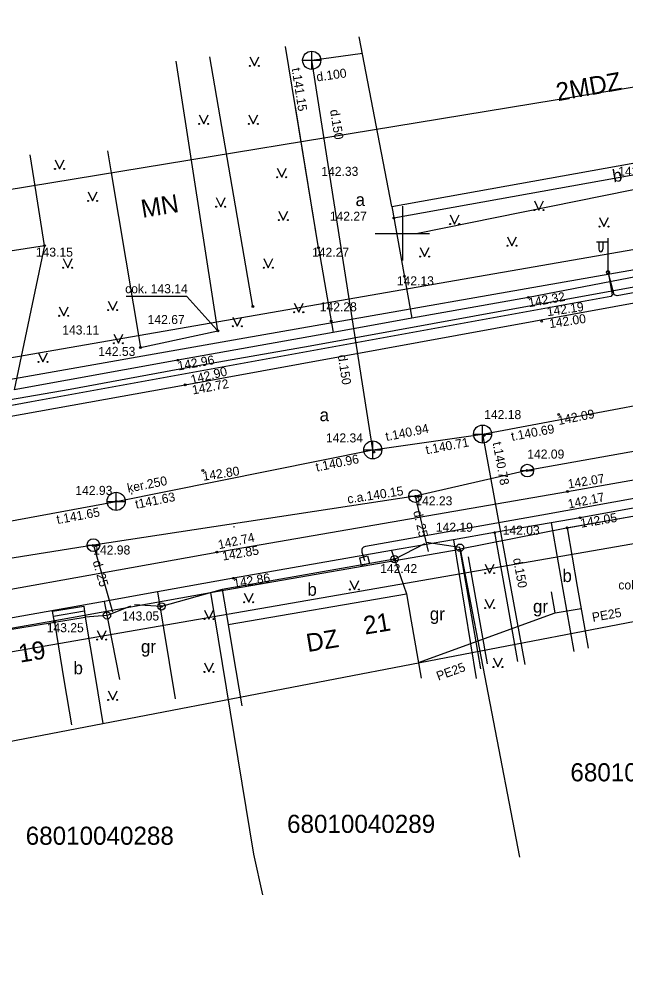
# Model space of a CAD drawing. Extents: x 728492 to 729038, y 272968 to 273171.
# Drawn here: x 728728.8 to 728762.3, y 273058.4 to 273111.8 of the extents above; entities that cross this region are included whole.
import ezdxf

# ---------------------------------------------------------------- set-up
doc = ezdxf.new("R2010")
doc.units = 0
for name, color, linetype in [('APGR_SARK_####_####_#', 7, 'Continuous'), ('APGS_ACRL_####_####_#', 7, 'Continuous'), ('APGS_ELEM_####_####_#', 7, 'Continuous'), ('APGS_VADP_ZSPR_####_I', 7, 'Continuous'), ('BUVE_BDET_####_####_#', 7, 'Continuous'), ('BUVE_BDET_####_TKST_#', 7, 'Continuous'), ('BUVE_EKAS_####_####_#', 7, 'Continuous'), ('BUVE_EKAS_ADRS_TKST_#', 7, 'Continuous'), ('BUVE_EKAS_RAKS_TKST_#', 7, 'Continuous'), ('CELI_CAPM_####_####_#', 7, 'Continuous'), ('CELI_CMAL_####_####_#', 7, 'Continuous'), ('CELI_CSEG_####_TKST_#', 7, 'Continuous'), ('CELI_SEGL_####_####_#', 7, 'Continuous'), ('ELEK_ELEM_####_####_#', 7, 'Continuous'), ('ELEK_VADP_ZSPR_####_I', 7, 'Continuous'), ('GEOD_ELEM_####_####_#', 7, 'Continuous'), ('NORB_ELEM_####_####_#', 7, 'Continuous'), ('NORB_ZOGS_BARJ_####_#', 7, 'Continuous'), ('NORB_ZOGS_KOKA_####_#', 7, 'Continuous'), ('NORB_ZOGS_ZSTP_####_#', 7, 'Continuous'), ('RAMI_UZMR_####_####_#', 7, 'Continuous'), ('RELJ_AATZ_####_TKST_#', 7, 'Continuous'), ('RELJ_ELEM_####_####_#', 7, 'Continuous'), ('ROBZ_KADS_####_TKST_#', 7, 'Continuous'), ('ROBZ_UZMR_####_####_#', 7, 'Continuous'), ('SKAN_ELEM_####_####_#', 7, 'Continuous'), ('SKAN_VADP_PAST_####_#', 7, 'Continuous'), ('SKAN_VADP_PAST_TKST_#', 7, 'Continuous'), ('TERT_DZOG_####_####_#', 7, 'Continuous'), ('TERT_ELEM_####_####_#', 7, 'Continuous'), ('TERT_KRND_####_####_#', 7, 'Continuous'), ('UDTK_ELEM_####_####_#', 7, 'Continuous'), ('UDTK_ELEM_####_TKST_#', 7, 'Continuous'), ('UDTK_VADP_UDEN_####_#', 7, 'Continuous'), ('UDTK_VADP_UDEN_TKST_#', 7, 'Continuous')]:
    doc.layers.add(name, color=color, linetype=linetype)

msp = doc.modelspace()

# ---------------------------------------------------------------- linework, layer by layer
at = {"layer": 'APGR_SARK_####_####_#'}
for points in [[(728813.011, 273107.831), (728678.847, 273084.513)], [(728815.186, 273091.969), (728680.999, 273068.647)]]:
    msp.add_lwpolyline(points, dxfattribs=at)
at = {"layer": 'APGS_ACRL_####_####_#'}
for points in [[(728789.256, 273101.647), (728780.318, 273100.005), (728761.848, 273096.552), (728761.682, 273096.617), (728761.349, 273097.858)], [(728761.587, 273096.618), (728761.498, 273096.52), (728729.511, 273090.707), (728708.292, 273086.771), (728707.787, 273088.186)]]:
    msp.add_lwpolyline(points, dxfattribs=at)
at = {"layer": 'APGS_ELEM_####_####_#'}
for p, q in [((728761.349, 273097.858), (728761.349, 273099.741)), ((728761.349, 273099.525), (728760.714, 273099.52)), ((728760.849, 273099.521), (728760.849, 273099.129)), ((728761.059, 273099.523), (728761.059, 273099.129))]:
    msp.add_line(p, q, dxfattribs=at)
msp.add_circle((728761.349, 273097.858), 0.09, dxfattribs=at)
msp.add_ellipse((728760.954, 273099.129), major_axis=(0, 0.151), ratio=0.695971, start_param=1.570796, end_param=4.712389, dxfattribs=at)
at = {"layer": 'APGS_VADP_ZSPR_####_I'}
for points in [[(728789.256, 273101.647), (728780.318, 273100.005), (728761.848, 273096.552), (728761.682, 273096.617), (728761.633, 273096.789), (728761.349, 273097.858)], [(728761.349, 273097.858), (728761.587, 273096.618), (728761.498, 273096.52), (728761.308, 273096.474), (728729.511, 273090.707), (728708.404, 273086.792), (728708.292, 273086.771), (728708.145, 273087.084), (728707.787, 273088.186)]]:
    msp.add_lwpolyline(points, dxfattribs=at)
at = {"layer": 'BUVE_BDET_####_####_#'}
for p, q in [((728730.676, 273079.135), (728732.399, 273079.421)), ((728732.399, 273079.421), (728732.475, 273078.816)), ((728730.776, 273078.534), (728730.676, 273079.135)), ((728730.72, 273078.871), (728732.447, 273079.158)), ((728730.776, 273078.534), (728732.475, 273078.816))]:
    msp.add_line(p, q, dxfattribs=at)
msp.add_lwpolyline([(728739.75, 273094.67), (728738.096, 273096.521), (728734.739, 273096.521)], dxfattribs=at)
at = {"layer": 'BUVE_EKAS_####_####_#'}
for p, q in [((728749.414, 273101.481), (728747.61, 273110.864)), ((728739.804, 273094.625), (728737.493, 273109.51)), ((728733.718, 273104.56), (728733.916, 273103.352)), ((728749.414, 273101.481), (728765.274, 273104.335)), ((728733.916, 273103.352), (728735.526, 273093.701)), ((728735.526, 273093.701), (728739.804, 273094.625)), ((728759.085, 273083.745), (728767.162, 273085.162)), ((728759.085, 273083.745), (728759.653, 273080.507)), ((728759.653, 273080.507), (728760.251, 273077.098)), ((728740.366, 273078.41), (728750.224, 273080.103)), ((728750.224, 273080.103), (728750.486, 273078.588)), ((728722.041, 273077.083), (728730.776, 273078.534)), ((728730.776, 273078.534), (728731.324, 273075.232)), ((728740.366, 273078.41), (728740.633, 273076.844)), ((728750.486, 273078.588), (728751.029, 273075.45)), ((728740.633, 273076.844), (728741.134, 273073.907)), ((728731.324, 273075.232), (728731.717, 273072.866))]:
    msp.add_line(p, q, dxfattribs=at)
at = {"layer": 'CELI_CAPM_####_####_#'}
for points in [[(728737.995, 273091.64), (728768.046, 273097.124)], [(728676.374, 273071.049), (728680.397, 273071.606), (728696.384, 273074.602), (728721.076, 273079.042), (728739.743, 273082.405), (728759.114, 273085.751), (728811.654, 273095.023), (728814.654, 273095.178), (728815.22, 273095.032), (728815.785, 273094.657), (728816.384, 273093.154), (728816.384, 273093.154), (728817.477, 273084.163), (728819.159, 273072.476)], [(728674.775, 273080.133), (728674.775, 273080.133), (728693.992, 273083.644), (728719.252, 273088.265), (728737.995, 273091.64)]]:
    msp.add_lwpolyline(points, dxfattribs=at)
at = {"layer": 'CELI_CMAL_####_####_#'}
for p, q in [((728745.365, 273099.211), (728744.092, 273106.987)), ((728729.653, 273102.952), (728729.434, 273104.338)), ((728749.527, 273100.854), (728765.387, 273103.708)), ((728730.227, 273099.328), (728729.653, 273102.952)), ((728749.414, 273101.481), (728750.517, 273095.315)), ((728730.227, 273099.328), (728728.55, 273091.364)), ((728745.365, 273099.211), (728746.177, 273094.537)), ((728768.84, 273098.755), (728756.958, 273096.471)), ((728756.958, 273096.471), (728750.517, 273095.315)), ((728746.177, 273094.537), (728737.596, 273092.997)), ((728737.596, 273092.997), (728728.55, 273091.364)), ((728769.324, 273086.003), (728759.807, 273084.302)), ((728759.807, 273084.302), (728758.212, 273084.024)), ((728758.212, 273084.024), (728758.863, 273080.342)), ((728755.09, 273083.479), (728752.823, 273083.083)), ((728755.09, 273083.479), (728755.759, 273079.692)), ((728749.397, 273082.485), (728740.663, 273080.96)), ((728740.663, 273080.96), (728736.464, 273080.209)), ((728758.863, 273080.342), (728759.467, 273076.921)), ((728733.529, 273079.685), (728721.657, 273077.563)), ((728755.759, 273079.692), (728756.349, 273076.355)), ((728732.475, 273078.816), (728733.022, 273075.526)), ((728733.022, 273075.526), (728733.452, 273072.937))]:
    msp.add_line(p, q, dxfattribs=at)
for points in [[(728745.365, 273099.211), (728743.546, 273110.32)], [(728752.823, 273083.083), (728754.06, 273075.427)], [(728749.397, 273082.485), (728750.224, 273080.103)], [(728736.464, 273080.209), (728737.455, 273074.296)], [(728733.529, 273079.685), (728734.366, 273075.373)]]:
    msp.add_lwpolyline(points, dxfattribs=at)
at = {"layer": 'CELI_SEGL_####_####_#'}
for p, q in [((728728.091, 273099.006), (728730.227, 273099.328)), ((728750.517, 273095.315), (728746.177, 273094.537)), ((728758.212, 273084.024), (728755.09, 273083.479)), ((728752.823, 273083.083), (728749.397, 273082.485)), ((728736.464, 273080.209), (728733.529, 273079.685))]:
    msp.add_line(p, q, dxfattribs=at)
at = {"layer": 'ELEK_ELEM_####_####_#'}
msp.add_lwpolyline([(728748.174, 273081.772), (728747.739, 273081.668), (728747.636, 273082.096), (728748.071, 273082.2)], close=True, dxfattribs=at)
at = {"layer": 'ELEK_VADP_ZSPR_####_I'}
for points in [[(728789.187, 273101.908), (728785.18, 273101.176), (728775.571, 273099.385), (728767.143, 273097.829), (728756.289, 273095.852), (728744.902, 273093.77), (728738.696, 273092.686), (728731.653, 273091.378), (728722.585, 273089.813), (728712.579, 273087.924)], [(728766.767, 273086.075), (728757.695, 273084.449), (728747.952, 273082.718)], [(728747.757, 273082.396), (728747.905, 273081.934)]]:
    msp.add_lwpolyline(points, dxfattribs=at)
msp.add_arc((728747.995, 273082.472), 0.25, 100.0738, 197.7532, dxfattribs=at)
at = {"layer": 'GEOD_ELEM_####_####_#'}
for p, q in [((728750, 273101.5), (728750, 273100)), ((728748.5, 273100), (728750, 273100)), ((728750, 273100), (728750, 273098.5)), ((728750, 273100), (728751.5, 273100))]:
    msp.add_line(p, q, dxfattribs=at)
at = {"layer": 'NORB_ELEM_####_####_#'}
for centre in [(728753.175, 273082.649), (728749.561, 273082.014), (728736.694, 273079.407), (728733.68, 273078.908)]:
    msp.add_circle(centre, 0.202, dxfattribs=at)
at = {"layer": 'NORB_ZOGS_BARJ_####_#'}
for points in [[(728749.561, 273082.014), (728751.228, 273082.884)], [(728753.175, 273082.649), (728751.318, 273082.94)], [(728733.68, 273078.908), (728734.997, 273079.442)], [(728736.694, 273079.407), (728735.199, 273079.483)], [(728733.68, 273078.908), (728732.475, 273078.816)]]:
    msp.add_lwpolyline(points, dxfattribs=at)
at = {"layer": 'NORB_ZOGS_KOKA_####_#'}
for points in [[(728754.332, 273075.958), (728753.175, 273082.649)], [(728749.561, 273082.014), (728740.038, 273080.333), (728740.366, 273078.41)]]:
    msp.add_lwpolyline(points, dxfattribs=at)
at = {"layer": 'NORB_ZOGS_ZSTP_####_#'}
msp.add_lwpolyline([(728740.038, 273080.333), (728736.694, 273079.407)], dxfattribs=at)
at = {"layer": 'RAMI_UZMR_####_####_#'}
msp.add_lwpolyline([(728688.721, 273058.407), (728702.149, 273066.922), (728733.452, 273072.937), (728813.127, 273088.247), (728815.181, 273072.879), (728831.342, 273076.994), (728831.817, 273091.35), (728930.137, 273106.573), (728962.389, 273111.567), (728966.363, 273103.835), (728988.796, 273109.153), (728985.811, 273141.417), (728955.146, 273144.603), (728957.616, 273137.975), (728904.333, 273130.641), (728847.677, 273120.095), (728823.483, 273119.793), (728790.036, 273112.558), (728726.814, 273102.175), (728686.914, 273096.216)], dxfattribs=at)
at = {"layer": 'RELJ_ELEM_####_####_#'}
for centre in [(728749.527, 273100.854), (728730.227, 273099.328), (728745.365, 273099.211), (728745.436, 273098.814), (728750.101, 273097.642), (728756.958, 273096.471), (728741.741, 273095.967), (728746.068, 273095.163), (728757.686, 273095.153), (728739.804, 273094.625), (728735.526, 273093.701), (728737.596, 273092.997), (728737.995, 273091.64), (728758.625, 273089.999), (728754.51, 273088.85), (728748.416, 273087.928), (728738.974, 273086.907), (728756.89, 273086.908), (728750.709, 273085.485), (728759.114, 273085.751), (728734.188, 273085.206), (728759.807, 273084.302), (728759.085, 273083.745), (728755.09, 273083.479), (728732.922, 273082.771), (728739.743, 273082.405), (728749.561, 273082.014), (728740.663, 273080.96), (728736.694, 273079.407), (728730.776, 273078.534)]:
    msp.add_circle(centre, 0.05, dxfattribs=at)
at = {"layer": 'ROBZ_UZMR_####_####_#'}
for p, q in [((728767.571, 273098.837), (728741.291, 273094.217)), ((728741.291, 273094.217), (728707.448, 273088.246)), ((728767.308, 273085.186), (728759.065, 273083.724)), ((728759.065, 273083.724), (728753.185, 273082.563)), ((728739.398, 273080.177), (728753.185, 273082.563)), ((728753.185, 273082.563), (728756.463, 273065.558)), ((728730.805, 273078.627), (728739.398, 273080.177)), ((728739.398, 273080.177), (728741.769, 273065.718)), ((728721.926, 273077.099), (728730.805, 273078.627)), ((728741.769, 273065.718), (728742.271, 273063.471))]:
    msp.add_line(p, q, dxfattribs=at)
at = {"layer": 'SKAN_ELEM_####_####_#'}
for p, q in [((728744.985, 273109.061), (728744.985, 273110.061)), ((728744.485, 273109.561), (728745.485, 273109.561)), ((728754.421, 273088.422), (728754.421, 273089.422)), ((728748.358, 273087.546), (728748.358, 273088.546)), ((728753.921, 273088.922), (728754.921, 273088.922)), ((728747.858, 273088.046), (728748.858, 273088.046)), ((728734.188, 273084.706), (728734.188, 273085.706)), ((728733.688, 273085.206), (728734.688, 273085.206))]:
    msp.add_line(p, q, dxfattribs=at)
for centre in [(728744.985, 273109.561), (728754.421, 273088.922), (728748.358, 273088.046), (728734.188, 273085.206)]:
    msp.add_circle(centre, 0.5, dxfattribs=at)
at = {"layer": 'SKAN_VADP_PAST_####_#'}
for points in [[(728720.316, 273082.646), (728734.188, 273085.206), (728748.358, 273088.046), (728744.985, 273109.561), (728747.785, 273109.953)], [(728754.421, 273088.922), (728770.492, 273091.941), (728805.243, 273097.85), (728806.524, 273091.029)], [(728748.358, 273088.046), (728754.421, 273088.922), (728756.747, 273076.191)]]:
    msp.add_lwpolyline(points, dxfattribs=at)
at = {"layer": 'TERT_DZOG_####_####_#'}
msp.add_lwpolyline([(728750.75, 273100), (728767.021, 273103.301)], dxfattribs=at)
at = {"layer": 'TERT_ELEM_####_####_#'}
for p, q in [((728741.569, 273109.75), (728741.819, 273109.25)), ((728741.819, 273109.25), (728742.069, 273109.75)), ((728738.772, 273106.55), (728739.022, 273106.05)), ((728739.022, 273106.05), (728739.272, 273106.55)), ((728741.512, 273106.55), (728741.762, 273106.05)), ((728741.762, 273106.05), (728742.012, 273106.55)), ((728730.811, 273104.065), (728731.061, 273103.565)), ((728731.061, 273103.565), (728731.311, 273104.065)), ((728743.082, 273103.608), (728743.332, 273103.108)), ((728743.332, 273103.108), (728743.582, 273103.608)), ((728732.637, 273102.294), (728732.887, 273101.794)), ((728732.887, 273101.794), (728733.137, 273102.294)), ((728739.714, 273101.979), (728739.964, 273101.479)), ((728739.964, 273101.479), (728740.214, 273101.979)), ((728757.281, 273101.794), (728757.531, 273101.294)), ((728757.531, 273101.294), (728757.781, 273101.794)), ((728743.168, 273101.237), (728743.418, 273100.737)), ((728743.418, 273100.737), (728743.668, 273101.237)), ((728752.629, 273101.022), (728752.879, 273100.522)), ((728752.879, 273100.522), (728753.129, 273101.022)), ((728760.877, 273100.879), (728761.127, 273100.379)), ((728761.127, 273100.379), (728761.377, 273100.879)), ((728755.797, 273099.822), (728756.047, 273099.322)), ((728756.047, 273099.322), (728756.297, 273099.822)), ((728750.973, 273099.222), (728751.223, 273098.722)), ((728751.223, 273098.722), (728751.473, 273099.222)), ((728731.267, 273098.609), (728731.517, 273098.109)), ((728731.517, 273098.109), (728731.767, 273098.609)), ((728742.34, 273098.608), (728742.59, 273098.108)), ((728742.59, 273098.108), (728742.84, 273098.608)), ((728733.75, 273096.266), (728734, 273095.766)), ((728734, 273095.766), (728734.25, 273096.266)), ((728744.024, 273096.151), (728744.274, 273095.651)), ((728744.274, 273095.651), (728744.524, 273096.151)), ((728731.039, 273095.952), (728731.289, 273095.452)), ((728731.289, 273095.452), (728731.539, 273095.952)), ((728740.628, 273095.38), (728740.878, 273094.88)), ((728740.878, 273094.88), (728741.128, 273095.38)), ((728734.064, 273094.438), (728734.314, 273093.938)), ((728734.314, 273093.938), (728734.564, 273094.438)), ((728729.897, 273093.409), (728730.147, 273092.909)), ((728730.147, 273092.909), (728730.397, 273093.409)), ((728754.561, 273081.74), (728754.811, 273081.24)), ((728754.811, 273081.24), (728755.061, 273081.74)), ((728747.096, 273080.839), (728747.346, 273080.339)), ((728747.346, 273080.339), (728747.596, 273080.839)), ((728741.259, 273080.134), (728741.509, 273079.634)), ((728741.509, 273079.634), (728741.759, 273080.134)), ((728754.561, 273079.812), (728754.811, 273079.312)), ((728754.811, 273079.312), (728755.061, 273079.812)), ((728739.059, 273079.206), (728739.309, 273078.706)), ((728739.309, 273078.706), (728739.559, 273079.206)), ((728733.143, 273078.076), (728733.393, 273077.576)), ((728733.393, 273077.576), (728733.643, 273078.076)), ((728739.059, 273076.285), (728739.309, 273075.785)), ((728739.309, 273075.785), (728739.559, 273076.285)), ((728755.021, 273076.56), (728755.271, 273076.06)), ((728755.271, 273076.06), (728755.521, 273076.56)), ((728733.747, 273074.738), (728733.997, 273074.238)), ((728733.997, 273074.238), (728734.247, 273074.738))]:
    msp.add_line(p, q, dxfattribs=at)
for centre, radius in [((728741.569, 273109.25), 0.028), ((728742.069, 273109.25), 0.0263), ((728738.772, 273106.05), 0.028), ((728739.272, 273106.05), 0.0263), ((728741.512, 273106.05), 0.028), ((728742.012, 273106.05), 0.0263), ((728730.81, 273103.565), 0.028), ((728731.31, 273103.565), 0.0263), ((728743.082, 273103.107), 0.028), ((728743.582, 273103.107), 0.0263), ((728732.637, 273101.794), 0.028), ((728733.137, 273101.794), 0.0263), ((728739.714, 273101.479), 0.028), ((728740.214, 273101.479), 0.0263), ((728757.281, 273101.293), 0.028), ((728757.781, 273101.293), 0.0263), ((728743.167, 273100.736), 0.028), ((728743.667, 273100.736), 0.0263), ((728752.628, 273100.522), 0.028), ((728753.128, 273100.522), 0.0263), ((728760.877, 273100.379), 0.028), ((728761.377, 273100.379), 0.0263), ((728755.796, 273099.322), 0.028), ((728756.296, 273099.322), 0.0263), ((728750.973, 273098.722), 0.028), ((728751.473, 273098.722), 0.0263), ((728731.267, 273098.108), 0.028), ((728731.767, 273098.108), 0.0263), ((728742.34, 273098.108), 0.028), ((728742.84, 273098.108), 0.0263), ((728731.039, 273095.451), 0.028), ((728731.539, 273095.451), 0.0263), ((728733.75, 273095.766), 0.028), ((728734.25, 273095.766), 0.0263), ((728744.024, 273095.651), 0.028), ((728744.524, 273095.651), 0.0263), ((728740.627, 273094.879), 0.028), ((728741.127, 273094.879), 0.0263), ((728734.064, 273093.937), 0.028), ((728734.564, 273093.937), 0.0263), ((728729.897, 273092.909), 0.028), ((728730.397, 273092.909), 0.0263), ((728754.561, 273081.24), 0.028), ((728755.061, 273081.24), 0.0263), ((728747.095, 273080.339), 0.028), ((728747.595, 273080.339), 0.0263), ((728741.259, 273079.634), 0.028), ((728741.759, 273079.634), 0.0263), ((728754.561, 273079.312), 0.028), ((728755.061, 273079.312), 0.0263), ((728739.059, 273078.705), 0.028), ((728739.559, 273078.705), 0.0263), ((728733.143, 273077.576), 0.028), ((728733.643, 273077.576), 0.0263), ((728739.059, 273075.784), 0.028), ((728739.559, 273075.784), 0.0263), ((728755.021, 273076.059), 0.028), ((728755.521, 273076.059), 0.0263), ((728733.747, 273074.237), 0.028), ((728734.247, 273074.237), 0.0263)]:
    msp.add_circle(centre, radius, dxfattribs=at)
at = {"layer": 'TERT_KRND_####_####_#'}
for points in [[(728741.741, 273095.967), (728739.355, 273109.759)], [(728754.701, 273076.233), (728753.649, 273082.137)]]:
    msp.add_lwpolyline(points, dxfattribs=at)
at = {"layer": 'UDTK_ELEM_####_####_#'}
for p, q in [((728756.539, 273086.908), (728757.241, 273086.908)), ((728756.889, 273086.908), (728756.889, 273086.909)), ((728750.344, 273085.496), (728751.046, 273085.496)), ((728750.694, 273085.496), (728750.694, 273085.497)), ((728732.582, 273082.788), (728733.284, 273082.788)), ((728732.932, 273082.788), (728732.932, 273082.789))]:
    msp.add_line(p, q, dxfattribs=at)
for centre in [(728756.89, 273086.908), (728750.695, 273085.496), (728732.933, 273082.788)]:
    msp.add_circle(centre, 0.351, dxfattribs=at)
at = {"layer": 'UDTK_VADP_UDEN_####_#'}
for p, q in [((728750.695, 273085.496), (728732.933, 273082.788)), ((728750.695, 273085.496), (728751.42, 273082.431)), ((728732.933, 273082.788), (728714.148, 273079.76)), ((728732.933, 273082.788), (728733.99, 273079.113)), ((728758.429, 273079.041), (728758.224, 273080.208)), ((728750.879, 273076.316), (728758.429, 273079.041)), ((728758.429, 273079.041), (728759.866, 273079.293))]:
    msp.add_line(p, q, dxfattribs=at)
msp.add_lwpolyline([(728771.523, 273089.532), (728756.89, 273086.908), (728750.695, 273085.496)], dxfattribs=at)

# ---------------------------------------------------------------- texts
at = {"layer": 'BUVE_BDET_####_TKST_#'}
for s, p in [('cok. 143.14', (728734.684, 273096.699)), ('cok. 142.76', (728761.921, 273080.341))]:
    msp.add_text(s, height=0.49999, dxfattribs=at).set_placement(p)
at = {"layer": 'BUVE_EKAS_ADRS_TKST_#'}
for s, p in [('21', (728747.934, 273077.844)), ('19', (728728.884, 273076.295))]:
    msp.add_text(s, height=1, rotation=9.431, dxfattribs=at).set_placement(p)
at = {"layer": 'BUVE_EKAS_RAKS_TKST_#'}
for s, rotation, p in [('2MDZ', 10.201, (728758.578, 273107.302)), ('MN', 9.298, (728735.646, 273100.856)), ('DZ', 9.431, (728744.773, 273076.88))]:
    msp.add_text(s, height=1, rotation=rotation, dxfattribs=at).set_placement(p)
at = {"layer": 'CELI_CSEG_####_TKST_#'}
msp.add_text('b', height=0.7, rotation=10.201, dxfattribs=at).set_placement((728761.664, 273102.816))
for s, p in [('a', (728747.409, 273101.515)), ('a', (728745.421, 273089.634)), ('b', (728758.832, 273080.751)), ('b', (728744.749, 273079.992)), ('gr', (728757.205, 273079.06)), ('gr', (728751.508, 273078.643)), ('gr', (728735.555, 273076.839)), ('b', (728731.833, 273075.655))]:
    msp.add_text(s, height=0.7, dxfattribs=at).set_placement(p)
at = {"layer": 'RELJ_AATZ_####_TKST_#'}
for s, p in [(' 142.33', (728745.331, 273103.179)), (' 142.03', (728761.726, 273103.183)), (' 142.27', (728745.8, 273100.703)), (' 143.15', (728729.568, 273098.718)), (' 142.27', (728744.82, 273098.711)), (' 142.13', (728749.504, 273097.134)), (' 142.28', (728745.247, 273095.699)), (' 142.67', (728735.742, 273094.998)), (' 143.11', (728731.025, 273094.42)), (' 142.53', (728733.017, 273093.237)), (' 142.19', (728751.656, 273083.527)), (' 142.03', (728755.348, 273083.363)), (' 142.42', (728748.58, 273081.242)), (' 143.05', (728734.33, 273078.625)), (' 143.25', (728730.168, 273077.979))]:
    msp.add_text(s, height=0.5, dxfattribs=at).set_placement(p)
for s, rotation, p in [('142.32', 10.0688, (728756.999, 273095.927)), ('142.19', 8.359, (728758.012, 273095.428)), ('142.00', 8.5088, (728758.137, 273094.767)), ('142.96', 10.0534, (728737.63, 273092.433)), ('142.90', 14.0474, (728738.374, 273091.67)), ('142.72', 10.4526, (728738.43, 273091.105)), ('142.09', 11.1128, (728758.632, 273089.419)), ('142.80', 8.7062, (728739.003, 273086.342)), ('142.07', 9.3068, (728759.17, 273085.911)), ('142.17', 11.7219, (728759.188, 273084.803)), ('142.05', 9.3606, (728759.864, 273083.748)), ('142.74', 12.2638, (728739.871, 273082.561)), ('142.85', 9.7354, (728740.088, 273081.932)), ('142.86', 9.2677, (728740.704, 273080.427))]:
    msp.add_text(s, height=0.5, rotation=rotation, dxfattribs=at).set_placement(p)
at = {"layer": 'ROBZ_KADS_####_TKST_#'}
for s, p in [('68010040059', (728759.272, 273069.745)), ('68010040289', (728743.625, 273066.898)), ('68010040288', (728729.194, 273066.242))]:
    msp.add_text(s, height=1, dxfattribs=at).set_placement(p)
at = {"layer": 'SKAN_ELEM_####_####_#'}
for s, p in [('142.18', (728754.51, 273089.747)), ('142.34', (728745.773, 273088.46)), ('142.93', (728731.934, 273085.56))]:
    msp.add_text(s, height=0.5, dxfattribs=at).set_placement(p)
at = {"layer": 'SKAN_VADP_PAST_TKST_#'}
for s, rotation, p in [('t.141.15', 278.91, (728743.877, 273109.104)), ('d.100', 7.984, (728745.282, 273108.392)), ('d.150', 278.91, (728745.999, 273106.808)), ('d.150', 278.91, (728746.423, 273093.266)), ('t.140.94', 11.333, (728749.114, 273088.532)), ('t.140.69', 10.642, (728756.047, 273088.54)), ('t.140.71', 10.642, (728751.327, 273087.799)), ('t.140.78', 280.352, (728754.973, 273088.441)), ('t.140.96', 11.333, (728745.262, 273086.847)), ('ķer.250', 11.333, (728734.852, 273085.682)), ('t141.63', 11.333, (728735.295, 273084.793)), ('t.141.65', 10.456, (728730.946, 273083.947)), ('d.150', 280.352, (728756.102, 273082.034))]:
    msp.add_text(s, height=0.5, rotation=rotation, dxfattribs=at).set_placement(p)
at = {"layer": 'UDTK_ELEM_####_TKST_#'}
for s, p in [('142.09', (728756.89, 273087.566)), ('142.23', (728750.709, 273084.985)), ('142.98', (728732.922, 273082.271))]:
    msp.add_text(s, height=0.5, dxfattribs=at).set_placement(p)
at = {"layer": 'UDTK_VADP_UDEN_TKST_#'}
for s, rotation, p in [('c.a.140.15', 8.6686, (728746.989, 273085.083)), ('d. 25', 283.3082, (728750.59, 273084.639)), ('.', 8.6686, (728740.61, 273083.748)), ('d. 25', 286.0462, (728732.885, 273081.87)), ('PE25', 9.951, (728760.516, 273078.553)), ('PE25', 19.845, (728751.982, 273075.301))]:
    msp.add_text(s, height=0.5, rotation=rotation, dxfattribs=at).set_placement(p)

doc.saveas('drawing.dxf')
